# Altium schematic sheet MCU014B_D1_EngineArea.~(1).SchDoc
size 558 x 431 mm; Date: Not shown in title block; ApprovedBy: Not shown in title block; CheckedBy: Not shown in title block; Author: Not shown in title block; CompanyName: Not shown in title block; DrawnBy: Vince Rodriguez; Engineer: Vince Rodriguez; Organization: Not shown in title block; Address1: Not shown in title block; Address2: Not shown in title block; Address3: Not shown in title block; Address4: Not shown in title block; DocumentNumber: 3; Revision: Use project parameter SCH_Rev; SheetNumber: 3; SheetTotal: 7; PageSetup: Record=PageOptions¦CenterHorizontal=True¦CenterVertical=True¦PrintScale=1.00¦XCorrection=1.00¦YCorrection=1.00¦PrintKind=0¦BorderSize=5000000¦LeftOffset=0¦BottomOffset=0¦Orientation=2¦PaperLength=1000¦PaperWidth=1000¦Scale=100¦PaperSource=15¦PrintQuality=600¦MediaType=1¦DitherType=10¦PaperKind=Letter¦PrintScaleMode=1
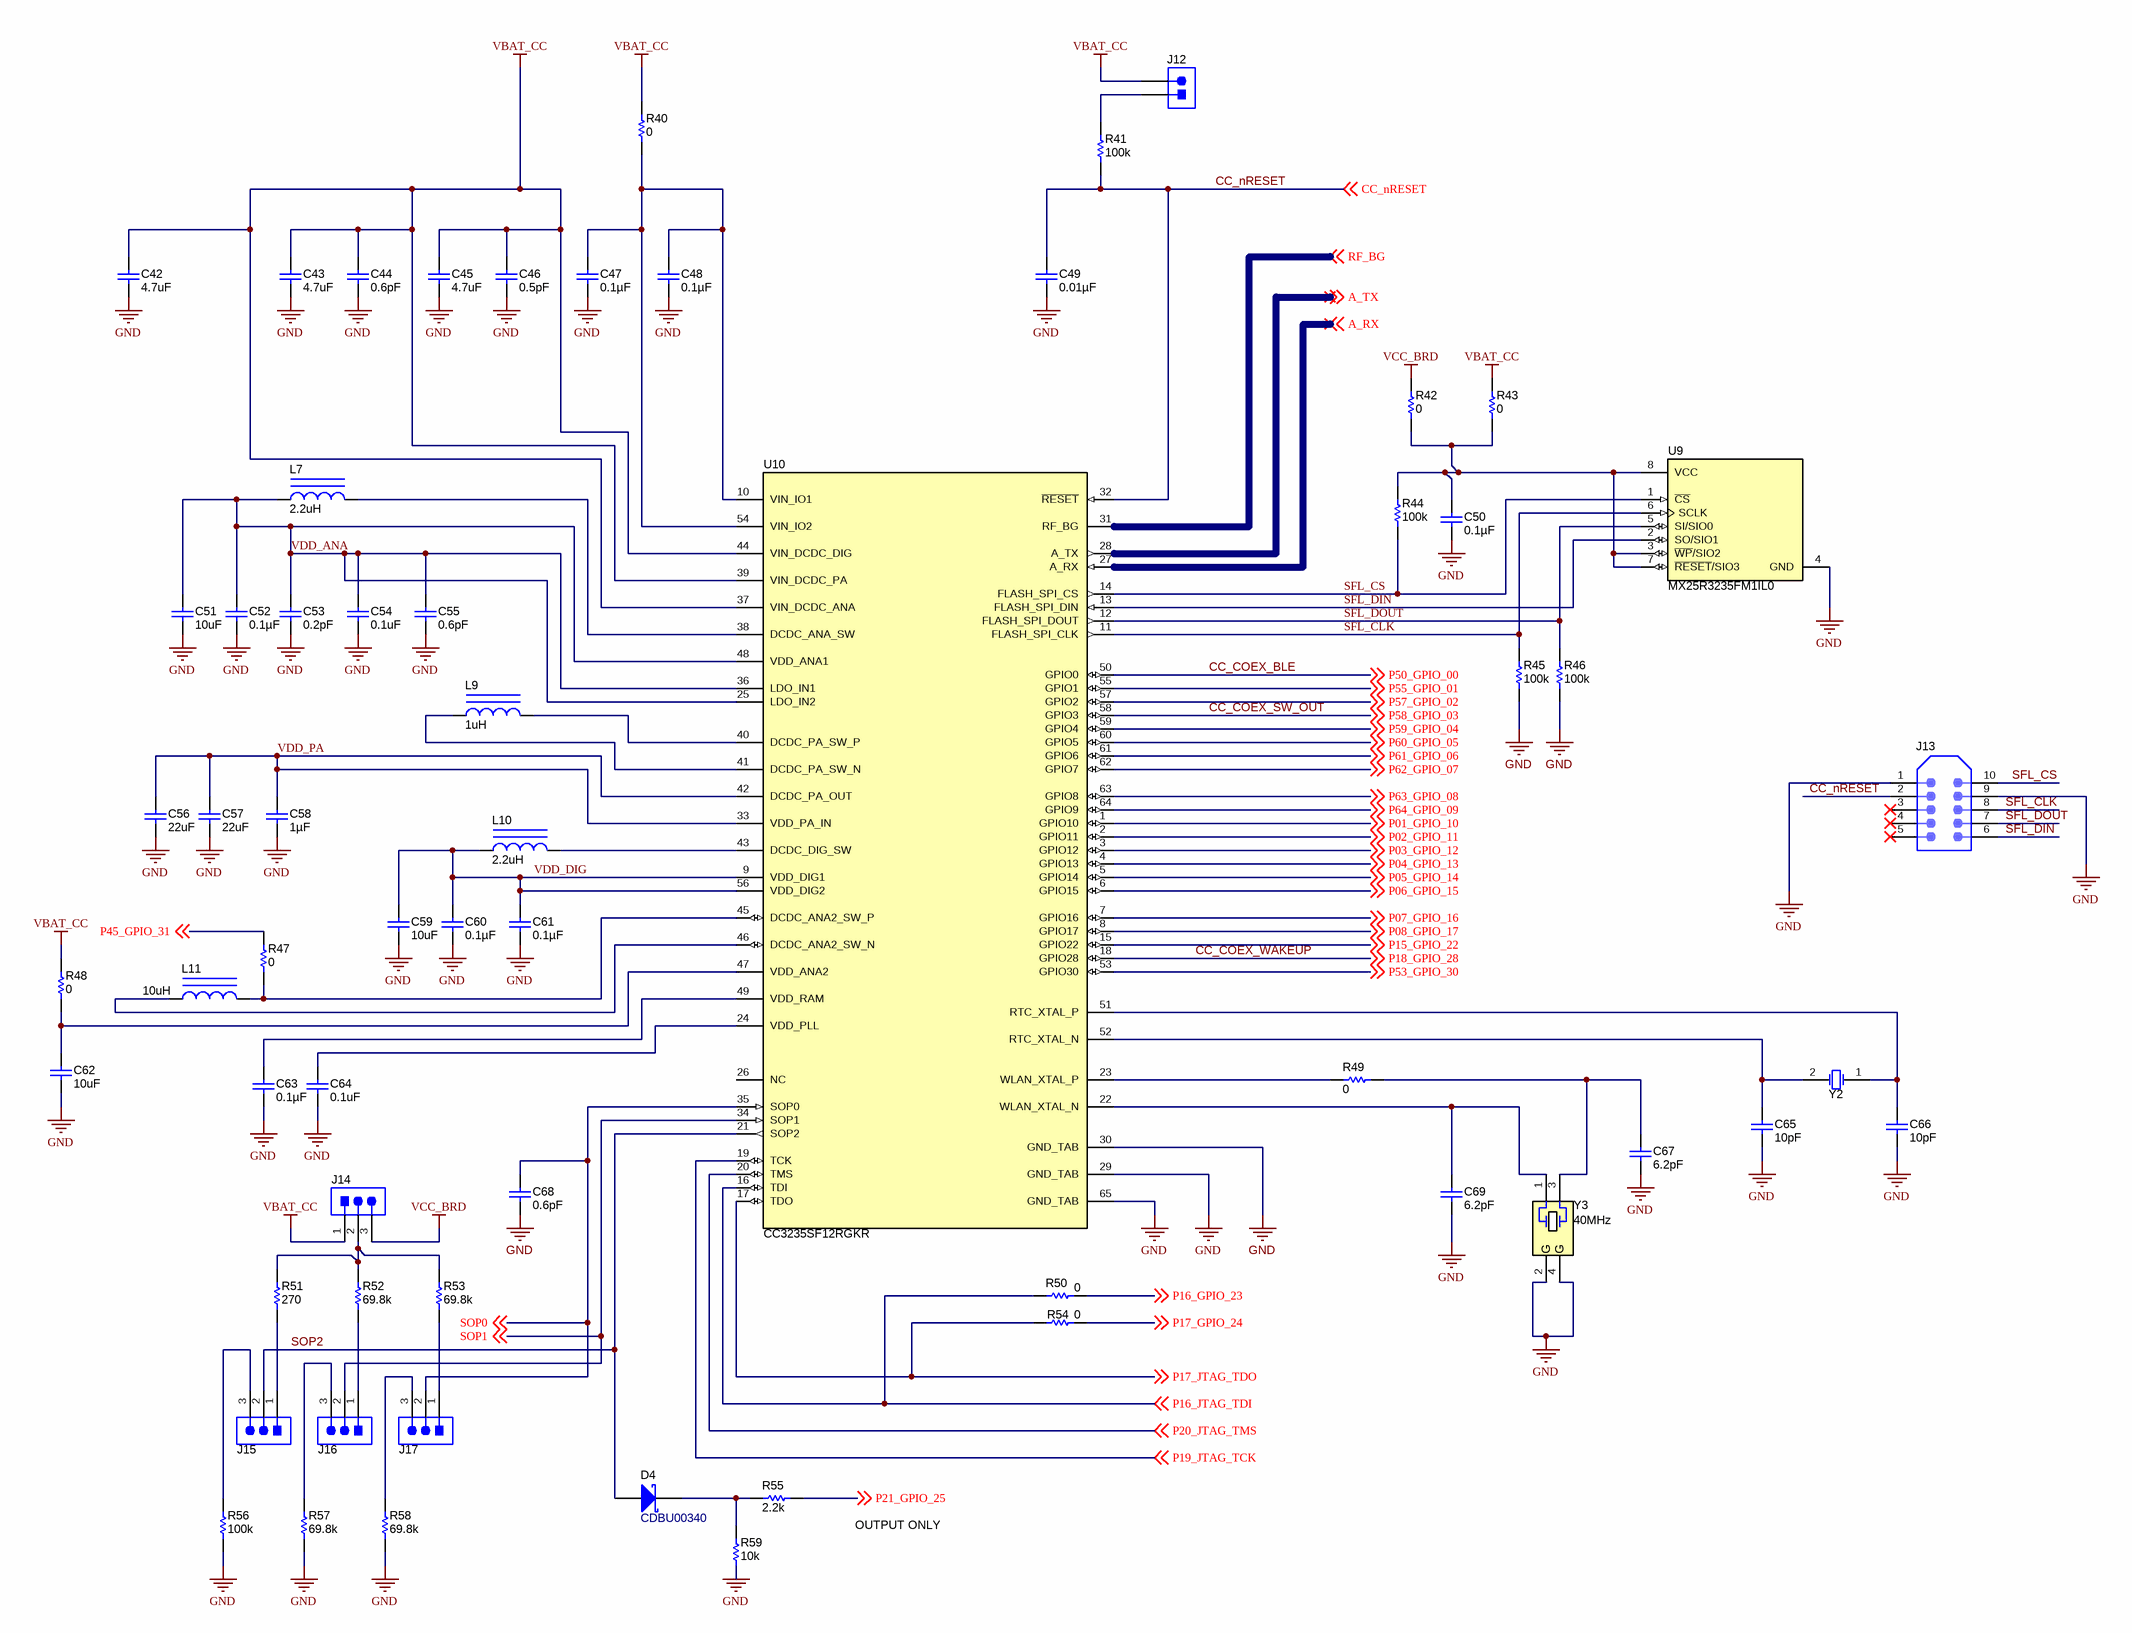
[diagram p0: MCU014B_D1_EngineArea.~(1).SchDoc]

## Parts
C42  ValueDisplayed: 4.7uF  [0402]  (hidden comment: CMP-0064972-2)
C43  ValueDisplayed: 4.7uF  [0402]  (hidden comment: CMP-0064972-2)
C44  ValueDisplayed: 0.6pF  [0201_033]  (hidden comment: GJM0335C1ER60BB01D)
C45  ValueDisplayed: 4.7uF  [0402]  (hidden comment: CMP-0064972-2)
C46  ValueDisplayed: 0.5pF  [0201_033]  (hidden comment: GJM0335C1ER50BB01D)
C47  ValueDisplayed: 0.1µF  [0402S]  (hidden comment: CL05B104KO5NNNC)
C48  ValueDisplayed: 0.1µF  [0402S]  (hidden comment: CL05B104KO5NNNC)
C49  ValueDisplayed: 0.01µF  [0402S]  (hidden comment: 0402B103K500CT)
C50  ValueDisplayed: 0.1µF  [0402S]  (hidden comment: CL05B104KO5NNNC)
C51  ValueDisplayed: 10uF  [0603]  (hidden comment: CMP-0064953-4)
C52  ValueDisplayed: 0.1µF  [0402S]  (hidden comment: CL05B104KO5NNNC)
C53  ValueDisplayed: 0.2pF  [0201_033]  (hidden comment: GJM0335C1ER20BB01D)
C54  ValueDisplayed: 0.1uF  [0201]  (hidden comment: CL03A104KP3NNNC)
C55  ValueDisplayed: 0.6pF  [0201_033]  (hidden comment: GJM0335C1ER60BB01D)
C56  ValueDisplayed: 22uF  [0603]  (hidden comment: CMP-0064952-4)
C57  ValueDisplayed: 22uF  [0603]  (hidden comment: CMP-0064952-4)
C58  ValueDisplayed: 1µF  [0402S]  (hidden comment: CL05A105MP5NNNC)
C59  ValueDisplayed: 10uF  [0603]  (hidden comment: CMP-0064953-4)
C60  ValueDisplayed: 0.1µF  [0402S]  (hidden comment: CL05B104KO5NNNC)
C61  ValueDisplayed: 0.1µF  [0402S]  (hidden comment: CL05B104KO5NNNC)
C62  ValueDisplayed: 10uF  [0603]  (hidden comment: CMP-0064953-4)
C63  ValueDisplayed: 0.1µF  [0402S]  (hidden comment: CL05B104KO5NNNC)
C64  ValueDisplayed: 0.1uF  [0201]  (hidden comment: CMP-0009655-3)
C65  ValueDisplayed: 10pF  [0402S]  (hidden comment: 0402N100J500CT)
C66  ValueDisplayed: 10pF  [0402S]  (hidden comment: 0402N100J500CT)
C67  ValueDisplayed: 6.2pF  [0402S]  (hidden comment: 0402N6R2C500CT)
C68  ValueDisplayed: 0.6pF  [0201_033]  (hidden comment: GJM0335C1ER60BB01D)
C69  ValueDisplayed: 6.2pF  [0402S]  (hidden comment: 0402N6R2C500CT)
D4  CDBU00340  [SOD-523F]
J12  CMP-0054794-1  [WURTH_61300211121]  (value not drawn)
J13  TC2050-IDC-NL-FP  [Tag_TC2050-NL]  (value not drawn)  (no BOM)
J14  CMP-0054796-1  [WURTH_61300311121]  (value not drawn)
J15  CMP-0054796-1  [WURTH_61300311121]  (value not drawn)
J16  CMP-0054796-1  [WURTH_61300311121]  (value not drawn)
J17  CMP-0054796-1  [WURTH_61300311121]  (value not drawn)
L7  ValueDisplayed: 2.2uH  [LQM2MPN_G0]  (hidden comment: CMP-0058761-1)
L9  ValueDisplayed: 1uH  [1008]  (hidden comment: CMP-0058750-1)
L10  ValueDisplayed: 2.2uH  [LQM2MPN_G0]  (hidden comment: CMP-0058761-1)
L11  ValueDisplayed: 10uH  [MLP2520S-M]  (hidden comment: CMP-0062710-1)
R40  ValueDisplayed: 0  [0603]  (hidden comment: CMP-0025874-3)
R41  ValueDisplayed: 100k  [0402]  (hidden comment: CMP-0026823-3)
R42  ValueDisplayed: 0  [0402]  (hidden comment: CMP-0026992-2)
R43  ValueDisplayed: 0  [0402]  (hidden comment: CMP-0026992-2)
R44  ValueDisplayed: 100k  [0402]  (hidden comment: CMP-0026823-3)
R45  ValueDisplayed: 100k  [0402]  (hidden comment: CMP-0026823-3)
R46  ValueDisplayed: 100k  [0402]  (hidden comment: CMP-0026823-3)
R47  ValueDisplayed: 0  [0402]  (hidden comment: CMP-0026992-2)
R48  ValueDisplayed: 0  [0402]  (hidden comment: CMP-0026992-2)
R49  ValueDisplayed: 0  [0402]  (hidden comment: CMP-0026992-2)
R50  ValueDisplayed: 0  [0402]  (hidden comment: CMP-0026992-2)
R51  ValueDisplayed: 270  [0402]  (hidden comment: CMP-0026886-3)
R52  ValueDisplayed: 69.8k  [0402]  (hidden comment: CMP-0026510-2)
R53  ValueDisplayed: 69.8k  [0402]  (hidden comment: CMP-0026510-2)
R54  ValueDisplayed: 0  [0402]  (hidden comment: CMP-0026992-2)
R55  ValueDisplayed: 2.2k  [0402]  (hidden comment: CMP-0026890-5)
R56  ValueDisplayed: 100k  [0402]  (hidden comment: CMP-0026823-3)
R57  ValueDisplayed: 69.8k  [0402]  (hidden comment: CMP-0026510-2)
R58  ValueDisplayed: 69.8k  [0402]  (hidden comment: CMP-0026510-2)
R59  ValueDisplayed: 10k  [0402]  (hidden comment: CMP-0026825-5)
U9  PartNumber: MX25R3235FM1IL0  [SOP-8_150MIL]  (hidden comment: CMP-0004903-1)
U10  CC3235SF12RGKR  [RGK0064B]
Y2  CMP-0004575-3  [XTAL_ABS07]  (value not drawn)
Y3  Frequency_Fixed: 40MHz  [TXC_8Y]  (hidden comment: 8Y40072002)

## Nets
GND: C42.2 C43.2 C44.2 C45.2 C46.2 C47.2 C48.2 C49.2 C50.2 C51.2 C52.2 C53.2 C54.2 C55.2 C56.2 C57.2 C58.2 C59.2 C60.2 C61.2 C62.2 C63.2 C64.2 C65.2 C66.2 C67.2 C68.2 C69.2 J13.1 J13.9 R45.2 R46.2 R56.2 R57.2 R58.2 R59.2 U9.4(GND) U10.29(GND_TAB) U10.30(GND_TAB) U10.65(GND_TAB) Y3.2(GND) Y3.4(GND)
VBAT_CC: C42.1 C43.1 C44.1 C45.1 C46.1 J12.2 J14.1 R40.2 R43.2 R48.2 U10.37(VIN_DCDC_ANA) U10.39(VIN_DCDC_PA) U10.44(VIN_DCDC_DIG)
VCC_BRD: J14.3 R42.2
A_RX: U10.27(A_RX) ; off-sheet A_RX
A_TX: U10.28(A_TX) ; off-sheet A_TX
CC_COEX_BLE: U10.50(GPIO0) ; off-sheet P50_GPIO_00  [also labelled P50_GPIO_00]
CC_COEX_SW_OUT: U10.58(GPIO3) ; off-sheet P58_GPIO_03  [also labelled P58_GPIO_03]
CC_COEX_WAKEUP: U10.18(GPIO28) ; off-sheet P18_GPIO_28  [also labelled P18_GPIO_28]
CC_nRESET: C49.1 J13.2 R41.2 U10.32(~{RESET}) ; off-sheet CC_nRESET
P01_GPIO_10: U10.1(GPIO10) ; off-sheet P01_GPIO_10
P02_GPIO_11: U10.2(GPIO11) ; off-sheet P02_GPIO_11
P03_GPIO_12: U10.3(GPIO12) ; off-sheet P03_GPIO_12
P04_GPIO_13: U10.4(GPIO13) ; off-sheet P04_GPIO_13
P05_GPIO_14: U10.5(GPIO14) ; off-sheet P05_GPIO_14
P06_GPIO_15: U10.6(GPIO15) ; off-sheet P06_GPIO_15
P07_GPIO_16: U10.7(GPIO16) ; off-sheet P07_GPIO_16
P08_GPIO_17: U10.8(GPIO17) ; off-sheet P08_GPIO_17
P15_GPIO_22: U10.15(GPIO22) ; off-sheet P15_GPIO_22
P16_GPIO_23: R50.2 ; off-sheet P16_GPIO_23
P16_JTAG_TDI: R50.1 U10.16(TDI) ; off-sheet P16_JTAG_TDI
P17_GPIO_24: R54.2 ; off-sheet P17_GPIO_24
P17_JTAG_TDO: R54.1 U10.17(TDO) ; off-sheet P17_JTAG_TDO
P19_JTAG_TCK: U10.19(TCK) ; off-sheet P19_JTAG_TCK
P20_JTAG_TMS: U10.20(TMS) ; off-sheet P20_JTAG_TMS
P21_GPIO_25: R55.2 ; off-sheet P21_GPIO_25
P45_GPIO_31: R47.1 ; off-sheet P45_GPIO_31
P53_GPIO_30: U10.53(GPIO30) ; off-sheet P53_GPIO_30
P55_GPIO_01: U10.55(GPIO1) ; off-sheet P55_GPIO_01
P57_GPIO_02: U10.57(GPIO2) ; off-sheet P57_GPIO_02
P59_GPIO_04: U10.59(GPIO4) ; off-sheet P59_GPIO_04
P60_GPIO_05: U10.60(GPIO5) ; off-sheet P60_GPIO_05
P61_GPIO_06: U10.61(GPIO6) ; off-sheet P61_GPIO_06
P62_GPIO_07: U10.62(GPIO7) ; off-sheet P62_GPIO_07
P63_GPIO_08: U10.63(GPIO8) ; off-sheet P63_GPIO_08
P64_GPIO_09: U10.64(GPIO9) ; off-sheet P64_GPIO_09
RF_BG: U10.31(RF_BG) ; off-sheet RF_BG
SFL_CLK: J13.8 R45.1 U9.6(SCLK) U10.11(FLASH_SPI_CLK)
SFL_CS: J13.10 R44.2 U9.1(~{CS}) U10.14(FLASH_SPI_CS)
SFL_DIN: J13.6 U9.2(SO/SIO1) U10.13(FLASH_SPI_DIN)
SFL_DOUT: J13.7 R46.1 U9.5(SI/SIO0) U10.12(FLASH_SPI_DOUT)
SOP0: C68.1 J17.2 U10.35(SOP0) ; off-sheet SOP0
SOP1: J16.2 U10.34(SOP1) ; off-sheet SOP1
SOP2: D4.2(A) J15.2 U10.21(SOP2)
VDD_ANA: C51.1 C52.1 C53.1 C54.1 C55.1 L7.1 U10.25(LDO_IN2) U10.36(LDO_IN1) U10.48(VDD_ANA1)
VDD_DIG: C59.1 C60.1 C61.1 L10.1 U10.9(VDD_DIG1) U10.56(VDD_DIG2)
VDD_PA: C56.1 C57.1 C58.1 U10.33(VDD_PA_IN) U10.42(DCDC_PA_OUT)
NetC47_1: C47.1 C48.1 R40.1 U10.10(VIN_IO1) U10.54(VIN_IO2)
NetC50_1: C50.1 R42.1 R43.1 R44.1 U9.3(~{WP}/SIO2) U9.7(~{RESET}/SIO3) U9.8(VCC)
NetC62_1: C62.1 R48.1 U10.47(VDD_ANA2)
NetC63_1: C63.1 U10.49(VDD_RAM)
NetC64_1: C64.1 U10.24(VDD_PLL)
NetC65_1: C65.1 U10.52(RTC_XTAL_N) Y2.2(OSC2)
NetC66_1: C66.1 U10.51(RTC_XTAL_P) Y2.1(OSC1)
NetC67_1: C67.1 R49.1 Y3.3
NetC69_1: C69.1 U10.22(WLAN_XTAL_N) Y3.1
NetD4_1: D4.1(K) R55.1 R59.1
NetJ12_1: J12.1 R41.1
NetJ14_2: J14.2 R51.1 R52.1 R53.1
NetJ15_1: J15.1 R51.2
NetJ15_3: J15.3 R56.1
NetJ16_1: J16.1 R52.2
NetJ16_3: J16.3 R57.1
NetJ17_1: J17.1 R53.2
NetJ17_3: J17.3 R58.1
NetL7_2: L7.2 U10.38(DCDC_ANA_SW)
NetL9_1: L9.1 U10.41(DCDC_PA_SW_N)
NetL9_2: L9.2 U10.40(DCDC_PA_SW_P)
NetL10_2: L10.2 U10.43(DCDC_DIG_SW)
NetL11_1: L11.1 U10.46(DCDC_ANA2_SW_N)
NetL11_2: L11.2 R47.2 U10.45(DCDC_ANA2_SW_P)
NetR49_2: R49.2 U10.23(WLAN_XTAL_P)

Not connected (* = marked no-connect by the designer): J13 3* 4* 5*; U10 26(NC)

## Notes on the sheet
- OUTPUT ONLY

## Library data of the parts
C42 C43 C45 = CMP-0064972-2: CAP, CERM, 4.7 uF, 6.3 V,+/- 20%, X6S, 0402; PartNumber: JMK105BC6475MV-F; Manufacturer: Taiyo Yuden; Alternate PartNumber: CL05A475MQ5NRNC; Alternate Manufacturer: SAMSUNG; Polarized: N; CompType: Capacitor; Value: 4.7uF; U/M: EA; Cap_F: 4.7µF; Value1: Unknown; VDC_V: 6.3V; TaMin_C: -55°C; TaMax_C: 105°C; SizeArea_mm2: 0.5; SizeAreaWB_mm2: 3; SizeX_mm: 1; SizeZ_mm: 0.6; AEC Category: Q200
C44 C55 C68 = CMP-0085407-1: CAP, CERM, 0.6pF, 25 V,+/- 16%, C0G/NP0, 0201; Manufacturer: MuRata; Polarized: N; U/M: EA; VDC_V: 25V; TaMin_C: -55°C; TaMax_C: 125°C; Cap_Case: 0201; SizeArea_mm2: 0.18; SizeAreaWB_mm2: 2.08; SizeX_mm: 0.6; SizeY_mm: 0.3; SizeZ_mm: 0.33; AEC Category: Q200
C46 = CMP-0085408-1: CAP, CERM, 0.5 pF, 25 V,+/- 20%, C0G/NP0, 0201; Manufacturer: MuRata; Polarized: N; Value: 0.5pF; U/M: EA; VDC_V: 25V; TaMin_C: -55°C; TaMax_C: 125°C; Cap_Case: 0201; SizeArea_mm2: 0.18; SizeAreaWB_mm2: 2.08; SizeX_mm: 0.6; SizeY_mm: 0.3; SizeZ_mm: 0.33; AEC Category: Q200
C47 C48 C50 C52 C60 C61 C63 = CMP-0085850-1: CAP, CERM, 0.1 µF, 16 V,+/- 10%, X7R, 0402; Manufacturer: Walsin; Alternate PartNumber: C1005X5R1A104K050BA; Polarized: N; Value: 0.1uF; U/M: EA; Cap_F: 100nF; VDC_V: 16V; TaMin_C: -55°C; TaMax_C: 125°C; Cap_Case: 0402; SizeArea_mm2: 0.5; SizeAreaWB_mm2: 3; SizeX_mm: 1; SizeZ_mm: 0.6; AEC Category: Q200
C49 = CMP-0085842-1: CAP, CERM, 0.01 µF, 50 V,+/- 10%, X7R, 0402; Manufacturer: Walsin; Alternate PartNumber: GRM155R71E103KA01D; Polarized: N; Value: 0.01uF; U/M: EA; Cap_F: 10nF; VDC_V: 50V; TaMin_C: -55°C; TaMax_C: 125°C; Cap_Case: 0402; SizeArea_mm2: 0.5; SizeAreaWB_mm2: 3; SizeX_mm: 1; SizeZ_mm: 0.6; AEC Category: Q200
C51 C59 C62 = CMP-0064953-4: CAP, CERM, 10 uF, 10 V,+/- 20%, X6S, 0603; PartNumber: LMK107BC6106MA-T; Manufacturer: Taiyo Yuden; Alternate PartNumber: CL10A106MP8NNNC; Alternate Manufacturer: SAMSUNG; Polarized: N; CompType: Capacitor; Value: 10uF; U/M: EA; Cap_F: 10µF; Value1: Unknown; VDC_V: 10V; TaMin_C: -55°C; TaMax_C: 105°C; SizeArea_mm2: 1.28; SizeAreaWB_mm2: 4.68; SizeX_mm: 1.6; SizeY_mm: 0.8; SizeZ_mm: 1; AEC Category: Q200
C53 = CMP-0085602-1: CAP, CERM, 0.2pF, 25 V,+/- 50%, C0G/NP0, 0201; Manufacturer: MuRata; Polarized: N; U/M: EA; VDC_V: 25V; TaMin_C: -55°C; TaMax_C: 125°C; Cap_Case: 0201; SizeArea_mm2: 0.18; SizeAreaWB_mm2: 2.08; SizeX_mm: 0.6; SizeY_mm: 0.3; SizeZ_mm: 0.33; AEC Category: Q200
C54 = CMP-0009655-3: CAP, CERM, 0.1 uF, 10 V, +/- 10%, X5R, 0201; Manufacturer: Samsung Electro-Mechanics; Polarized: N; Value: 0.1uF; U/M: EA; Cap_F: 100nF; Value1: Unknown; VDC_V: 10V; TaMin_C: -55°C; TaMax_C: 85°C; SizeArea_mm2: 0.18; SizeAreaWB_mm2: 2.08; SizeX_mm: 0.6; SizeY_mm: 0.3; SizeZ_mm: 0.26; AEC Category: Q200
C56 C57 = CMP-0064952-4: CAP, CERM, 22 uF, 4 V,+/- 20%, X6S, 0603; PartNumber: GRM188C80G226ME15J; Manufacturer: MuRata; Alternate PartNumber: CL10A226MQ8NRNC; Alternate Manufacturer: SAMSUNG; Polarized: N; CompType: Capacitor; Value: 22uF; U/M: EA; Cap_F: 22µF; Value1: Unknown; VDC_V: 4V; TaMin_C: -55°C; TaMax_C: 105°C; SizeArea_mm2: 1.28; SizeAreaWB_mm2: 4.68; SizeX_mm: 1.6; SizeY_mm: 0.8; SizeZ_mm: 1; AEC Category: Q200
C58 = CMP-0085849-1: CAP, CERM, 1 µF, 10 V,+/- 20%, X5R, 0402; Manufacturer: Walsin; Alternate PartNumber: GRM155C81A105KA12D; Polarized: N; Value: 1uF; U/M: EA; VDC_V: 10V; TaMin_C: -55°C; TaMax_C: 85°C; Cap_Case: 0402; SizeArea_mm2: 0.5; SizeAreaWB_mm2: 3; SizeX_mm: 1; SizeZ_mm: 0.6; AEC Category: Q200
C64 = CMP-0009655-3: CAP, CERM, 0.1 uF, 10 V, +/- 10%, X5R, 0201; PartNumber: CL03A104KP3NNNC; Manufacturer: Samsung Electro-Mechanics; Polarized: N; Value: 0.1uF; U/M: EA; Cap_F: 100nF; Value1: Unknown; VDC_V: 10V; TaMin_C: -55°C; TaMax_C: 85°C; SizeArea_mm2: 0.18; SizeAreaWB_mm2: 2.08; SizeX_mm: 0.6; SizeY_mm: 0.3; SizeZ_mm: 0.26; AEC Category: Q200
C65 C66 = CMP-0085843-1: CAP, CERM, 10 pF, 50 V,+/- 5%, C0G/NP0, 0402; Manufacturer: Walsin; Alternate PartNumber: GRM1555C1H100JA01D; Polarized: N; Value: 10pF; U/M: EA; VDC_V: 50V; TaMin_C: -55°C; TaMax_C: 125°C; Cap_Case: 0402; SizeAreaWB_mm2: 3; SizeZ_mm: 0.6; SizeX_mm: 1; SizeY_mm: 0.5; AEC Category: Q200
C67 C69 = CMP-0085844-1: CAP, CERM, 6.2 pF, 50 V,+/- 4%, C0G/NP0, 0402; Manufacturer: Walsin; Alternate PartNumber: GRM1555C1H6R2CA01D; Polarized: N; Value: 6.2pF; U/M: EA; VDC_V: 50V; TaMin_C: -55°C; TaMax_C: 125°C; Cap_Case: 0402; SizeAreaWB_mm2: 3; SizeZ_mm: 0.6; SizeX_mm: 1; SizeY_mm: 0.5; AEC Category: Q200
D4 = CMP-0081923-2: Diode, Schottky, 45 V, 0.03 A, SOD-523F; Manufacturer: Comchip Technology; Alternate PartNumber: CD0603-B00340; Vf_V: 370mV; Value: 45V; Value1: 0.03A; Value2: 0.37V; Io_A: 30mA; TJmax_C: 125°C; AEC Category: Q101; AEC Qualified: N; SizeAreaWB_mm2: 5.13; SizeZ_mm: 0.85; SizeX_mm: 1.7; SizeY_mm: 0.9; SizeArea_mm2: 1.53
J12 = CMP-0054794-1: Header, 2.54 mm, 2x1, Gold, TH; PartNumber: 61300211121; Manufacturer: Wurth Elektronik; Alternate Manufacturer: ----; CNHeader: TRUE; Green_Lifecycle: Active; Green_REACh: Passed; CT: FALSE
J13 = CMP-0075101-1: Footprint for Tag-Connect TC2050 No-Legs cables; CompType: Receptacle; Note: Footprint only, to mate with Tag-Connect TC2050 No-Legs cables; CT: False
J14-J17 = CMP-0054796-1: Header, 2.54 mm, 3x1, Gold, TH; PartNumber: 61300311121; Manufacturer: Wurth Elektronik; Alternate Manufacturer: ----; CNHeader: TRUE; Green_Lifecycle: Active; Green_REACh: Passed; CT: FALSE
L7 L10 = CMP-0058761-1: Inductor, Multilayer, Ferrite, 2.2 uH, 1.2 A, 0.11 ohm, SMD; PartNumber: LQM2MPN2R2NG0; Manufacturer: MuRata; Alternate PartNumber: ----; Value: 2.2uH; Ind_H: 2.2µH; Imax_A: 1.2A; Irms: 1.2A @ 40C rise; DCR_ohm: 1.1d; SizeAreaWB_mm2: 7.8; SizeArea_mm2: 3.2; SizeX_mm: 2; SizeY_mm: 1.6; SizeZ_mm: 1; AEC Category: Q200; AEC Qualified: N
L9 = CMP-0058750-1: Inductor, Multilayer, Ferrite, 1 uH, 1.6 A, 0.055 ohm, SMD; PartNumber: LQM2HPN1R0MG0L; Manufacturer: MuRata; Alternate PartNumber: ----; Value: 1uH; Ind_H: 1µH; Imax_A: 1.6A; Irms: 1.6A @ 40C rise; DCR_ohm: 0.055; Green_Lifecycle: Active; SizeAreaWB_mm2: 10.5; Green_REACh: Passed; SizeZ_mm: 1.2; SizeX_mm: 2.5; SizeY_mm: 2; SizeArea_mm2: 5; AEC Category: Q200
L11 = CMP-0062710-1: Inductor, Multilayer, Ferrite, 10 uH, 0.7 A, 0.364 ohm, SMD; PartNumber: MLP2520S100MT0S1; Manufacturer: TDK; Alternate PartNumber: ----; Value: 10uH; Ind_H: 10µH; Imax_A: 7dA; Irms: 0.7A @ 40C rise; DCR_ohm: 3.64d; Value2: 0.7A; SizeAreaWB_mm2: 11.84; SizeArea_mm2: 5.94; SizeX_mm: 2.7; SizeY_mm: 2.2; SizeZ_mm: 1; AEC Category: Q200; AEC Qualified: N
R40 = CMP-0025874-3: RES, 0, 5%, 0.1 W, 0603; PartNumber: ERJ-3GEY0R00V; Manufacturer: Panasonic; Alternate Manufacturer: YAGEO; Alternate PartNumber: RC0603FR-070RL; Value: 0; Value_Code: 0000; Power_W: 100mW; Value2: 0.1W; VDC_V: 50V; TempCo: 600 ppm/C; EIA_Code: E24; U/M: EA; SizeX_mm: 1.6; SizeY_mm: 0.8; SizeZ_mm: 1; SizeArea_mm2: 1.28; AEC Category: Q200
R41 = CMP-0026823-3: RES, 100 k, 5%, 0.063 W, AEC-Q200 Grade 0, 0402; PartNumber: CRCW0402100KJNED; Manufacturer: Vishay-Dale; Alternate Manufacturer: YAGEO; Alternate PartNumber: RC0402JR-07100KL; Value: 100k; Power_W: 63mW; Value2: 0.063W; VDC_V: 50V; TempCo: 200 ppm/C; EIA_Code: E24; SizeArea_mm2: 0.5; SizeX_mm: 1; SizeZ_mm: 0.6; AEC Category: Q200; AEC Qualified: Y; AEC Grade: 0
R42 R43 R54 = CMP-0026992-2: RES, 0, 5%, 0.063 W, 0402; PartNumber: ERJ-2GE0R00X; Manufacturer: Panasonic; Alternate Manufacturer: YAGEO; Alternate PartNumber: RC0402JR-070RL; Value: 0; Value_Code: 0000; Power_W: 63mW; Value2: 0.063W; VDC_V: 50V; TempCo: 600 ppm/C; EIA_Code: E24; U/M: EA; AEC Category: Q200; SizeX_mm: 1; SizeY_mm: 0.5; SizeZ_mm: 0.6
R44-R46 R56 = CMP-0026823-3: RES, 100 k, 5%, 0.063 W, AEC-Q200 Grade 0, 0402; PartNumber: CRCW0402100KJNED; Manufacturer: Vishay-Dale; Alternate Manufacturer: YAGEO; Alternate PartNumber: RC0402JR-07100KL; Value: 100k; Power_W: 63mW; Value2: 0.063W; VDC_V: 50V; TempCo: 200 ppm/C; EIA_Code: E24; SizeX_mm: 1; SizeY_mm: 0.5; SizeZ_mm: 0.6; AEC Qualified: Y; AEC Category: Q200; AEC Grade: 0
R47-R50 = CMP-0026992-2: RES, 0, 5%, 0.063 W, 0402; PartNumber: ERJ-2GE0R00X; Manufacturer: Panasonic; Alternate Manufacturer: YAGEO; Alternate PartNumber: RC0402JR-070RL; Value: 0; Value_Code: 0000; Power_W: 63mW; Value2: 0.063W; VDC_V: 50V; TempCo: 600 ppm/C; EIA_Code: E24; U/M: EA; SizeX_mm: 1; SizeY_mm: 0.5; SizeZ_mm: 0.6; AEC Category: Q200
R51 = CMP-0026886-3: RES, 270, 5%, 0.063 W, AEC-Q200 Grade 0, 0402; PartNumber: CRCW0402270RJNED; Manufacturer: Vishay-Dale; Alternate Manufacturer: YAGEO; Alternate PartNumber: RC0402JR-07270RL; CompType: Resistor; Value: 270; Value_Code: 270R; Power_W: 63mW; Value2: 0.063W; VDC_V: 50V; TempCo: 200 ppm/C; EIA_Code: E24; SizeX_mm: 1; SizeY_mm: 0.5; SizeZ_mm: 0.6; AEC Qualified: Y; AEC Category: Q200; AEC Grade: 0
R52 R53 R57 R58 = CMP-0026510-2: RES, 69.8 k, 1%, 0.063 W, AEC-Q200 Grade 0, 0402; PartNumber: CRCW040269K8FKED; Manufacturer: Vishay-Dale; Alternate Manufacturer: YAGEO; Alternate PartNumber: RC0402FR-0769K8L; Value: 69.8k; Value_Code: 69k8; Power_W: 63mW; Value2: 0.063W; VDC_V: 50V; TempCo: 100 ppm/C; SizeArea_mm2: 0.5; SizeX_mm: 1; SizeZ_mm: 0.6; EIA_Code: E96; AEC Category: Q200; AEC Qualified: Y; AEC Grade: 0
R55 = CMP-0026890-5: RES, 2.2 k, 5%, 0.063 W, AEC-Q200 Grade 0, 0402; PartNumber: CRCW04022K20JNED; Manufacturer: Vishay-Dale; Alternate Manufacturer: YAGEO; Alternate PartNumber: RC0402JR-072K2L; CompType: Resistor; Value: 2.2k; Value_Code: 2k20; Power_W: 63mW; Value2: 0.063W; VDC_V: 50V; TempCo: 200 ppm/C; EIA_Code: E24; AEC Category: Q200; AEC Qualified: Y; AEC Grade: 0; SizeX_mm: 1; SizeY_mm: 0.5; SizeZ_mm: 0.6
R59 = CMP-0026825-5: RES, 10 k, 5%, 0.063 W, AEC-Q200 Grade 0, 0402; PartNumber: CRCW040210K0JNED; Manufacturer: Vishay-Dale; Alternate Manufacturer: YAGEO; Alternate PartNumber: RC0402JR-0710KL; Value: 10k; Value_Code: 10k0; Power_W: 63mW; Value2: 0.063W; VDC_V: 50V; TempCo: 200 ppm/C; EIA_Code: E24; SizeX_mm: 1; SizeY_mm: 0.5; SizeZ_mm: 0.6; AEC Qualified: Y; AEC Category: Q200; AEC Grade: 0
U9 = CMP-0004903-1: ULTRA LOW POWER, 32M-BIT [x 1/x 2/x 4] CMOS MXSMIO(SERIAL MULTI I/O) FLASH MEMORY, SOP-8; Manufacturer: Macronix International Co., LTD; Alternate Manufacturer: ----
U10 = CMP-0065220-6: SimpleLink Wi-Fi and Internet-of-Things Solution, a Single-Chip Wireless MCU, RGK0064B (VQFN-64); Manufacturer: Texas Instruments; CompType: IC; SizeArea_mm2: 81.0; SizeAreaWB_mm2: 121.0; SizeX_mm: 9.0; SizeZ_mm: 1.0; AEC Qualified: N; AEC Category: Q200
Y2 = CMP-0004575-3: CRYSTAL, 32.768KHz, 9PF, SMD; PartNumber: ABS07-32.768KHZ-9-T; Manufacturer: Abracon Corporation; Alternate Manufacturer: ----; TaMin_C: -40°C; TaMax_C: 85°C; Frequency Stability: +/-20ppm
Y3 = CMP-0077111-2: Crystal, 40 MHz, 8 pF, SMD; Manufacturer: TXC Corporation; Alternate Manufacturer: ----; Alternate PartNumber: Order Directly from TXC; TaMax_C: 95°C; TaMin_C: -40°C; U/M: EA; Frequency Stability: ±15ppm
